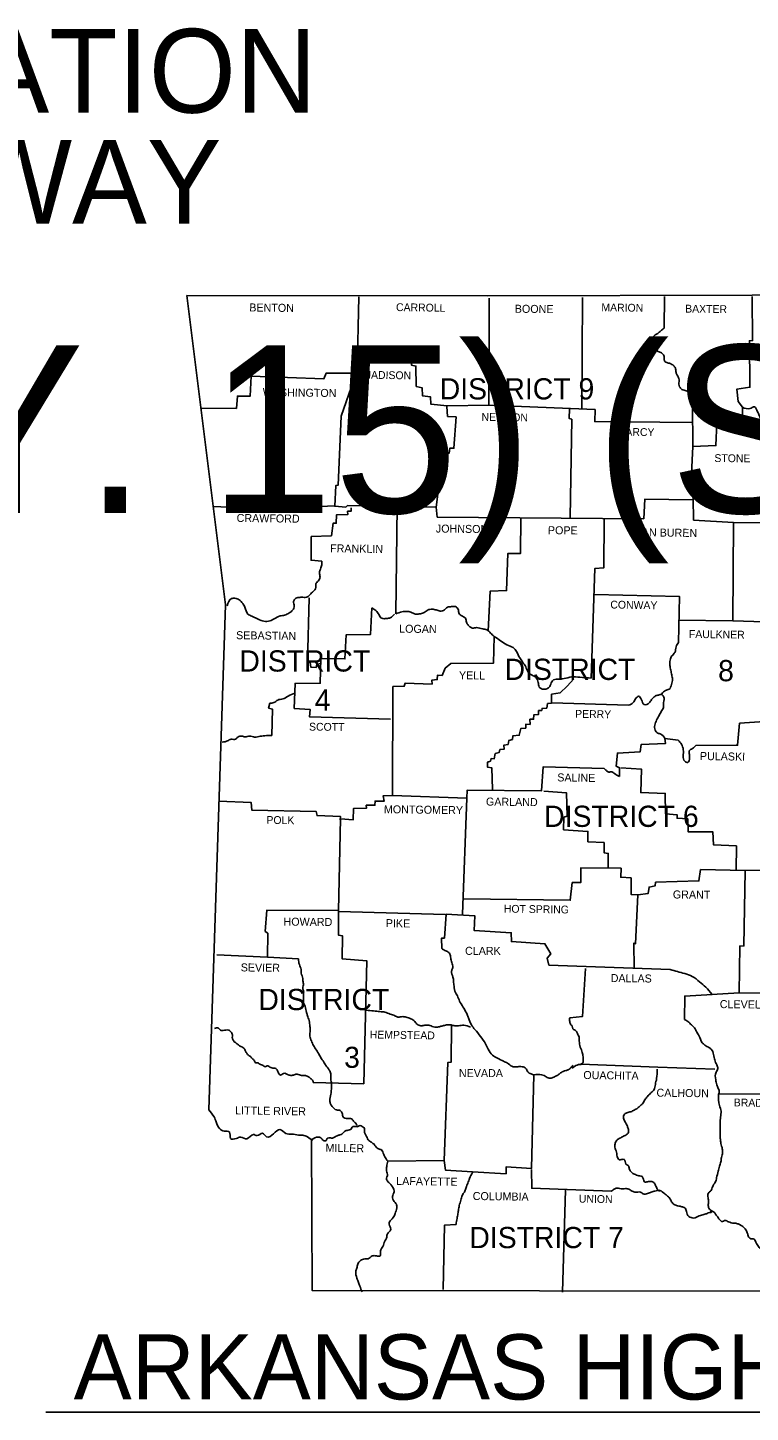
# Model space of a CAD drawing. Extents: x 1127717 to 1741049, y 2026793 to 2244711.
# Drawn here: x 1352440 to 1371845, y 2119549 to 2156746 of the extents above; entities that cross this region are included whole.
import ezdxf

# ---------------------------------------------------------------- set-up
doc = ezdxf.new("R2010")
doc.units = 0
doc.layers.add('R_Draft', color=7, linetype='Continuous')

msp = doc.modelspace()

# ---------------------------------------------------------------- linework, layer by layer
at = {"layer": 'R_Draft'}
msp.add_line((1352928, 2119549), (1385989, 2119549), dxfattribs=at)
for points in [[(1356715, 2149549), (1364800, 2149544), (1371895, 2149559), (1380265, 2149689), (1384145, 2149779)], [(1357300, 2127674), (1357750, 2141239), (1356715, 2149549)], [(1361330, 2149519), (1361285, 2147494)], [(1361320, 2147989), (1362550, 2147949), (1362580, 2147789), (1362750, 2147784), (1362745, 2147684), (1362865, 2147654), (1362875, 2147109), (1363030, 2147074), (1363040, 2146859), (1363260, 2146829), (1363270, 2146629), (1363705, 2146584), (1364825, 2146609), (1364835, 2149484)], [(1367340, 2149494), (1367325, 2146524)], [(1369540, 2149529), (1369530, 2148674)], [(1370380, 2137464), (1371505, 2137469), (1371555, 2138059), (1372225, 2138109), (1372225, 2140789), (1371375, 2140814), (1371390, 2143449), (1370320, 2143519), (1370305, 2144699), (1370270, 2144759), (1370300, 2145499), (1370920, 2145519), (1370945, 2146129), (1371625, 2146154), (1371635, 2146549), (1371515, 2146704), (1371485, 2147039), (1371835, 2147089), (1371820, 2148334), (1371905, 2148339), (1371895, 2149529)], [(1363435, 2143599), (1363410, 2143864), (1361025, 2143909), (1360980, 2143864), (1360685, 2143889), (1360715, 2144449), (1360775, 2144454), (1360855, 2146309), (1361260, 2147469), (1360455, 2147464), (1360395, 2147314), (1358445, 2147384), (1358415, 2146849), (1358070, 2146849), (1358045, 2146519), (1357110, 2146524)], [(1370300, 2145499), (1370295, 2146624)], [(1363695, 2146574), (1363715, 2146304), (1363945, 2146289), (1363885, 2145449), (1363780, 2145454), (1363760, 2145319), (1363640, 2145319), (1363635, 2145089), (1363560, 2145084), (1363535, 2144789), (1363425, 2144774), (1363410, 2144324), (1363460, 2144289), (1363410, 2143864)], [(1364825, 2146609), (1367675, 2146489), (1367670, 2146164), (1370285, 2146144)], [(1366990, 2146504), (1366985, 2146244), (1367050, 2146229), (1367010, 2143589)], [(1370300, 2144064), (1369010, 2144079), (1368985, 2143554), (1363435, 2143599)], [(1357440, 2143884), (1359715, 2143779), (1359725, 2143859), (1360675, 2143904)], [(1361125, 2143844), (1361125, 2143754), (1361030, 2143754), (1361035, 2143664), (1360730, 2143659), (1360725, 2143434), (1360640, 2143434), (1360595, 2143099), (1360055, 2143074), (1360050, 2142439), (1360340, 2142419)], [(1362325, 2140999), (1362360, 2143884)], [(1365680, 2143581), (1365675, 2142624), (1365330, 2142619), (1365300, 2141624), (1364860, 2141609), (1364808, 2140546)], [(1367920, 2143534), (1367910, 2142234), (1367670, 2142214), (1367575, 2139274)], [(1371390, 2143449), (1373960, 2143434), (1374180, 2143539), (1374165, 2141584), (1374015, 2141519), (1373880, 2141404), (1373835, 2141359), (1373830, 2140799), (1372195, 2140799)], [(1360000, 2141429), (1359950, 2139709), (1360025, 2139689), (1360040, 2139569), (1360190, 2139559), (1360205, 2139644), (1360325, 2139664)], [(1367660, 2141519), (1369945, 2141464), (1369915, 2140229)], [(1361680, 2141159), (1361645, 2140444), (1360995, 2140439), (1360960, 2139789), (1360315, 2139804), (1360295, 2139134), (1359620, 2139129), (1359600, 2138459), (1360025, 2138434), (1360010, 2138229), (1362180, 2138169)], [(1369920, 2140834), (1371375, 2140814)], [(1357515, 2131839), (1358880, 2131779), (1358885, 2132419), (1358815, 2132469), (1358860, 2133039), (1360785, 2133034), (1360840, 2135494), (1361180, 2135464), (1361185, 2135769), (1361535, 2135779), (1361530, 2135859), (1361765, 2135859), (1361770, 2135969), (1362010, 2135964), (1361990, 2136114), (1362240, 2136119), (1362250, 2139044), (1362550, 2139054), (1362575, 2139134), (1363300, 2139114), (1363295, 2139219), (1363440, 2139234), (1363445, 2139349), (1363570, 2139339), (1363655, 2139539), (1363805, 2139669), (1364945, 2139674), (1364965, 2140394)], [(1367110, 2139254), (1366930, 2139059), (1366735, 2138874), (1366510, 2138839), (1366510, 2138604), (1366400, 2138589), (1366380, 2138469), (1366255, 2138459), (1366245, 2138404), (1366160, 2138399), (1366155, 2138294), (1366035, 2138289), (1366025, 2138169), (1365925, 2138169), (1365930, 2138029), (1365820, 2138039), (1365815, 2137929), (1365680, 2137919), (1365640, 2137739), (1365470, 2137724), (1365455, 2137624), (1365365, 2137599), (1365340, 2137494), (1365225, 2137469), (1365235, 2137364), (1365120, 2137354), (1365100, 2137274), (1364995, 2137244), (1364970, 2137109), (1364890, 2137114), (1364865, 2137044), (1364790, 2137019), (1364785, 2136884), (1364900, 2136864), (1364920, 2136284)], [(1358995, 2137734), (1359010, 2138439), (1358910, 2138469), (1358940, 2138604)], [(1368575, 2138544), (1366515, 2138609)], [(1368330, 2136634), (1368330, 2136864), (1368240, 2136909), (1368275, 2137259), (1368890, 2137294), (1368910, 2137489), (1369565, 2137514), (1369550, 2137649), (1369910, 2137609)], [(1371480, 2137474), (1371505, 2137499)], [(1364230, 2136044), (1364240, 2136259), (1366240, 2136249), (1366285, 2136894), (1367920, 2136844)], [(1368365, 2136859), (1368925, 2136824), (1368905, 2136199), (1369560, 2136174), (1369570, 2135629), (1369880, 2135604), (1369880, 2135509), (1370170, 2135489), (1370180, 2135139), (1370840, 2135139), (1370860, 2134794), (1371470, 2134764), (1371465, 2134114)], [(1366300, 2136239), (1366905, 2136194), (1366925, 2135564), (1366840, 2135534), (1366830, 2135199), (1367485, 2135154), (1367485, 2134879), (1367920, 2134854), (1367925, 2134579), (1368030, 2134564), (1368025, 2134194)], [(1357575, 2135964), (1358440, 2135934), (1358460, 2135724), (1360190, 2135689), (1360210, 2135579), (1360840, 2135559), (1360835, 2135464)], [(1364230, 2136044), (1362240, 2136119)], [(1364115, 2132929), (1364230, 2136044)], [(1377430, 2134689), (1375540, 2134739), (1375530, 2134124), (1371705, 2134109)], [(1364150, 2133344), (1367010, 2133304), (1367065, 2133779), (1367290, 2133779), (1367295, 2134179), (1368375, 2134164), (1368365, 2133924), (1368645, 2133904), (1368645, 2133464), (1368825, 2133449)], [(1371705, 2134109), (1370510, 2134129), (1370465, 2133824), (1369300, 2133789), (1369290, 2133689), (1369125, 2133659), (1369105, 2133489), (1368825, 2133449)], [(1371705, 2134099), (1371675, 2132079), (1371560, 2132074), (1371545, 2130819)], [(1368825, 2133449), (1368765, 2132139), (1368720, 2132154), (1368725, 2131474)], [(1360785, 2133034), (1360785, 2132369), (1360895, 2132349), (1360885, 2131729), (1361545, 2131679), (1361465, 2128374), (1360105, 2128409)], [(1360795, 2132999), (1363655, 2132924)], [(1363560, 2132009), (1363550, 2132284), (1363630, 2132289), (1363680, 2132934), (1364450, 2132884), (1364430, 2132489), (1365425, 2132434), (1365430, 2132194), (1366330, 2132139), (1366485, 2131869), (1366390, 2131749), (1366435, 2131564), (1369695, 2131444)], [(1358880, 2131779), (1359710, 2131729)], [(1367415, 2131469), (1367340, 2130184), (1366995, 2130144)], [(1370825, 2130774), (1370085, 2130729), (1370080, 2130104)], [(1370815, 2130774), (1371545, 2130819)], [(1371545, 2130819), (1373315, 2130809)], [(1363825, 2129954), (1363815, 2128959), (1363725, 2128949), (1363625, 2126314)], [(1367290, 2128899), (1369360, 2128824), (1370895, 2128764)], [(1364385, 2126014), (1365285, 2125959), (1365290, 2126144), (1365965, 2126099), (1366030, 2128619)], [(1370995, 2128099), (1373255, 2128104)], [(1378400, 2122794), (1360075, 2122824), (1360065, 2126869)], [(1364385, 2126014), (1363660, 2126054), (1363625, 2126314), (1362110, 2126299)], [(1368110, 2125489), (1365975, 2125569), (1365965, 2126074)], [(1366885, 2125524), (1366805, 2122779)], [(1363600, 2122849), (1363635, 2124579), (1363945, 2124599)]]:
    msp.add_lwpolyline(points, dxfattribs=at)
for points in [[(1369530, 2148674), (1369440, 2148599), (1369360, 2148529), (1369240, 2148444), (1369225, 2148364), (1369265, 2148284), (1369305, 2148219), (1369320, 2148129), (1369355, 2148054), (1369440, 2148024), (1369510, 2147959), (1369535, 2147869), (1369545, 2147784), (1369625, 2147744), (1369715, 2147714), (1369800, 2147654), (1369840, 2147579), (1369850, 2147484), (1369885, 2147409), (1369925, 2147319), (1369935, 2147244), (1369925, 2147169), (1369945, 2147099), (1370010, 2147029), (1370125, 2146994), (1370205, 2146944), (1370260, 2146874), (1370225, 2146789), (1370230, 2146714), (1370275, 2146624)], [(1371635, 2146549), (1371835, 2146514), (1371955, 2146559), (1372040, 2146429), (1372085, 2146329), (1372160, 2146184), (1372280, 2146139), (1372370, 2146059), (1372370, 2145974), (1372290, 2145894), (1372230, 2145814), (1372250, 2145719), (1372270, 2145589), (1372270, 2145464), (1372240, 2145349), (1372215, 2145244), (1372240, 2145154), (1372335, 2145169), (1372435, 2145244), (1372540, 2145244), (1372640, 2145189), (1372745, 2145094), (1372850, 2145114), (1372935, 2145139), (1373055, 2145174), (1373140, 2145129), (1373215, 2145069), (1373305, 2144974), (1373390, 2144914), (1373500, 2144859), (1373635, 2144824), (1373760, 2144739), (1373780, 2144594), (1373775, 2144469), (1373765, 2144314), (1373755, 2144144), (1373770, 2143979), (1373825, 2143869), (1373895, 2143739), (1373915, 2143619), (1373910, 2143429)], [(1360340, 2142419), (1360340, 2142314), (1360300, 2142204), (1360275, 2142109), (1360290, 2141984), (1360245, 2141884), (1360180, 2141804), (1360180, 2141704), (1360105, 2141599), (1360025, 2141519), (1359955, 2141454), (1359830, 2141444), (1359725, 2141439), (1359620, 2141404), (1359580, 2141329), (1359600, 2141214), (1359560, 2141104), (1359455, 2141019), (1359340, 2140964), (1359220, 2140944), (1359055, 2140864), (1358905, 2140799), (1358745, 2140809), (1358595, 2140874), (1358460, 2140934), (1358355, 2140994), (1358270, 2141179), (1358215, 2141279), (1358120, 2141379), (1358005, 2141419), (1357910, 2141409), (1357795, 2141214)], [(1361680, 2141159), (1361790, 2141089), (1361875, 2140974), (1361950, 2140879), (1362075, 2140874), (1362175, 2140894), (1362290, 2140994)], [(1364965, 2140394), (1364870, 2140484), (1364770, 2140569), (1364660, 2140594), (1364490, 2140629), (1364380, 2140619), (1364315, 2140649), (1364270, 2140699), (1364225, 2140774), (1364200, 2140879), (1364115, 2140934), (1364020, 2141019), (1364005, 2141109), (1363930, 2141194), (1363825, 2141194), (1363705, 2141174), (1363635, 2141109), (1363515, 2141074), (1363405, 2141104), (1363300, 2141124), (1363190, 2141104), (1363090, 2141039), (1362990, 2141004), (1362855, 2140994), (1362730, 2141044), (1362610, 2141064), (1362490, 2141054), (1362325, 2140999)], [(1364965, 2140394), (1365140, 2140274), (1365305, 2140169), (1365475, 2140094), (1365570, 2139984), (1365655, 2139814), (1365725, 2139709), (1365815, 2139579), (1365880, 2139434), (1365985, 2139354), (1366095, 2139284), (1366150, 2139159), (1366175, 2139034), (1366295, 2138974), (1366410, 2138999), (1366475, 2139074), (1366535, 2139204), (1366670, 2139244), (1366845, 2139259), (1367045, 2139304), (1367265, 2139294), (1367575, 2139274)], [(1369915, 2140229), (1369850, 2140114), (1369820, 2139964), (1369740, 2139869), (1369690, 2139759), (1369685, 2139614), (1369710, 2139484), (1369735, 2139359), (1369755, 2139244), (1369730, 2139099), (1369665, 2138974), (1369565, 2138939), (1369470, 2138854)], [(1358940, 2138604), (1359050, 2138614), (1359155, 2138684), (1359295, 2138714), (1359435, 2138789), (1359610, 2138869)], [(1368575, 2138544), (1368700, 2138614), (1368765, 2138719), (1368845, 2138784), (1368925, 2138694), (1368995, 2138564), (1369070, 2138564), (1369165, 2138654), (1369225, 2138734), (1369300, 2138794), (1369380, 2138819), (1369465, 2138829), (1369530, 2138734), (1369510, 2138584), (1369510, 2138484), (1369455, 2138379), (1369395, 2138269), (1369330, 2138144), (1369280, 2138009), (1369290, 2137879), (1369360, 2137794), (1369440, 2137769), (1369550, 2137659)], [(1358995, 2137734), (1358850, 2137729), (1358685, 2137709), (1358535, 2137689), (1358400, 2137714), (1358275, 2137694), (1358190, 2137714), (1358085, 2137689), (1358025, 2137629), (1357900, 2137629), (1357810, 2137589), (1357665, 2137554)], [(1369910, 2137609), (1369995, 2137499), (1370045, 2137349), (1370045, 2137179), (1370085, 2137039), (1370165, 2137009), (1370215, 2137129), (1370205, 2137249), (1370205, 2137319), (1370290, 2137379), (1370380, 2137464)], [(1367920, 2136844), (1367980, 2136789), (1368045, 2136749), (1368125, 2136754), (1368200, 2136709), (1368330, 2136634)], [(1366030, 2128619), (1365960, 2128639), (1365870, 2128699), (1365820, 2128789), (1365715, 2128834), (1365600, 2128834), (1365445, 2128844), (1365325, 2128929), (1365220, 2128979), (1365055, 2129064), (1364925, 2129144), (1364810, 2129304), (1364735, 2129449), (1364600, 2129644), (1364450, 2129834), (1364355, 2129959), (1364280, 2130144), (1364240, 2130234), (1364155, 2130404), (1364055, 2130559), (1363995, 2130704), (1363930, 2130824), (1363890, 2130999), (1363875, 2131129), (1363860, 2131239), (1363820, 2131399), (1363850, 2131469), (1363840, 2131599), (1363805, 2131724), (1363785, 2131839), (1363735, 2131914), (1363640, 2131959), (1363560, 2132009)], [(1359710, 2131729), (1359735, 2131579), (1359780, 2131449), (1359785, 2131349), (1359830, 2131199), (1359830, 2131144), (1359845, 2131034), (1359825, 2130974), (1359850, 2130854), (1359845, 2130764), (1359845, 2130689), (1359850, 2130564), (1359890, 2130454), (1359930, 2130289), (1359955, 2130204), (1359995, 2130074), (1360020, 2129914), (1360025, 2129794), (1360015, 2129684), (1360045, 2129559), (1360100, 2129434), (1360170, 2129314), (1360255, 2129179), (1360315, 2129074), (1360390, 2128959), (1360450, 2128864), (1360540, 2128744), (1360580, 2128644), (1360580, 2128504), (1360600, 2128374), (1360595, 2128229), (1360585, 2128099), (1360550, 2127919), (1360575, 2127834), (1360670, 2127709), (1360730, 2127674), (1360835, 2127654), (1360885, 2127584), (1360915, 2127479), (1361020, 2127444), (1361135, 2127434), (1361190, 2127374), (1361265, 2127294), (1361290, 2127254)], [(1369695, 2131444), (1370085, 2131334), (1370285, 2131259), (1370485, 2131114), (1370650, 2130969), (1370815, 2130784)], [(1361535, 2130349), (1361725, 2130334), (1361900, 2130314), (1362035, 2130299), (1362175, 2130249), (1362300, 2130204), (1362380, 2130169), (1362515, 2130179), (1362630, 2130154), (1362760, 2130109), (1362855, 2130024), (1362915, 2129959), (1363030, 2129934), (1363125, 2129949), (1363240, 2129939), (1363370, 2129899), (1363475, 2129904), (1363560, 2129924), (1363660, 2129949), (1363785, 2129959), (1363880, 2129939), (1364005, 2129934), (1364150, 2129949), (1364330, 2129899)], [(1357455, 2129864), (1357565, 2129869), (1357640, 2129804), (1357685, 2129809), (1357765, 2129819), (1357840, 2129814), (1357895, 2129769), (1357940, 2129689), (1357935, 2129614), (1357940, 2129584), (1357975, 2129519), (1358035, 2129469), (1358100, 2129419), (1358160, 2129379), (1358260, 2129314), (1358270, 2129294), (1358310, 2129214), (1358360, 2129149), (1358420, 2129109), (1358485, 2129039), (1358515, 2129009), (1358565, 2128939), (1358620, 2128934), (1358695, 2128889), (1358750, 2128874), (1358810, 2128834), (1358870, 2128854), (1358945, 2128824), (1359045, 2128794), (1359100, 2128784), (1359165, 2128689), (1359230, 2128609), (1359310, 2128654), (1359460, 2128609), (1359555, 2128604), (1359640, 2128629), (1359705, 2128624), (1359825, 2128594), (1359900, 2128594), (1359980, 2128564), (1360055, 2128504), (1360105, 2128439), (1360105, 2128409)], [(1366995, 2130144), (1366995, 2130049), (1367030, 2129959), (1367065, 2129919), (1367080, 2129854), (1367125, 2129824), (1367190, 2129764), (1367225, 2129679), (1367250, 2129624), (1367250, 2129554), (1367255, 2129484), (1367265, 2129399), (1367325, 2129249), (1367340, 2129189), (1367350, 2129139), (1367355, 2129054), (1367355, 2128954), (1367290, 2128899)], [(1370080, 2130104), (1370195, 2130029), (1370290, 2129929), (1370360, 2129854), (1370405, 2129769), (1370465, 2129669), (1370550, 2129479), (1370625, 2129414), (1370730, 2129349), (1370795, 2129304), (1370860, 2129159), (1370890, 2129014), (1370945, 2128884), (1370970, 2128784), (1370925, 2128684), (1370915, 2128484), (1370945, 2128349), (1370985, 2128249), (1371010, 2128134), (1370995, 2128099)], [(1367085, 2128874), (1367030, 2128809), (1366965, 2128754), (1366890, 2128729), (1366820, 2128709), (1366730, 2128649), (1366660, 2128599), (1366565, 2128554), (1366475, 2128524), (1366365, 2128559), (1366305, 2128594), (1366240, 2128619), (1366030, 2128619)], [(1367065, 2128794), (1367195, 2128879), (1367340, 2128899)], [(1369340, 2128764), (1369330, 2128514), (1369295, 2128359), (1369260, 2128219), (1369185, 2128139), (1369105, 2128059), (1369030, 2127969), (1368965, 2127859), (1368900, 2127789), (1368815, 2127719), (1368730, 2127669), (1368635, 2127624), (1368530, 2127599), (1368455, 2127544), (1368450, 2127424), (1368535, 2127254), (1368565, 2127174), (1368575, 2127079), (1368540, 2127024), (1368460, 2126979), (1368365, 2126924), (1368280, 2126874), (1368220, 2126789), (1368210, 2126674), (1368250, 2126539), (1368265, 2126459), (1368330, 2126334), (1368380, 2126339), (1368470, 2126334), (1368480, 2126309), (1368485, 2126284), (1368505, 2126219), (1368580, 2126164), (1368590, 2126114), (1368635, 2126019), (1368710, 2125954), (1368765, 2125934), (1368880, 2125899), (1368940, 2125884), (1369005, 2125739), (1369085, 2125744), (1369145, 2125754), (1369245, 2125729), (1369290, 2125669), (1369335, 2125569), (1369395, 2125499), (1369435, 2125499)], [(1370995, 2128099), (1371015, 2127789), (1371060, 2127639), (1371045, 2127479), (1371040, 2127324), (1371040, 2127184), (1371040, 2127049), (1371040, 2126909), (1371050, 2126809), (1371085, 2126664), (1371100, 2126529), (1371070, 2126399), (1371055, 2126279), (1371015, 2126159), (1370980, 2126024), (1370940, 2125849), (1370905, 2125734), (1370835, 2125614), (1370790, 2125504), (1370720, 2125434), (1370710, 2125314), (1370725, 2125204), (1370715, 2125104), (1370750, 2125009), (1370840, 2124944)], [(1360065, 2126869), (1360085, 2126859), (1359990, 2126924), (1359860, 2126989), (1359715, 2126999), (1359530, 2127024), (1359375, 2127039), (1359215, 2127144), (1359045, 2127034), (1358855, 2126954), (1358745, 2127044), (1358600, 2126984), (1358500, 2127014), (1358325, 2126894), (1358160, 2126939), (1358040, 2126904), (1357890, 2126909), (1357860, 2127079), (1357715, 2127104), (1357590, 2127174), (1357505, 2127349), (1357445, 2127484), (1357300, 2127674)], [(1360065, 2126869), (1360240, 2126944), (1360315, 2126919), (1360380, 2126854), (1360455, 2126854), (1360495, 2126914), (1360570, 2126919), (1360630, 2126914), (1360695, 2126954), (1360750, 2126979), (1360825, 2127004), (1360880, 2127024), (1360930, 2127079), (1361020, 2127124), (1361125, 2127159), (1361155, 2127209), (1361205, 2127229), (1361305, 2127224), (1361370, 2127254), (1361425, 2127229), (1361475, 2127194), (1361485, 2127064), (1361525, 2126994), (1361585, 2126869), (1361670, 2126804), (1361750, 2126739), (1361780, 2126699), (1361865, 2126624), (1361940, 2126599), (1361975, 2126544), (1362030, 2126414), (1362110, 2126299)], [(1362110, 2126299), (1362080, 2126154), (1362075, 2126039), (1362100, 2125904), (1362075, 2125839), (1362115, 2125744), (1362190, 2125669), (1362245, 2125589), (1362280, 2125474), (1362235, 2125344), (1362285, 2125209), (1362330, 2125159), (1362355, 2125079), (1362320, 2124924), (1362275, 2124809), (1362175, 2124694), (1362145, 2124639), (1362160, 2124564), (1362185, 2124444), (1362160, 2124409), (1362095, 2124324), (1362075, 2124229), (1362030, 2124149), (1361980, 2124004), (1361915, 2123884), (1361905, 2123749), (1361805, 2123749), (1361690, 2123749), (1361585, 2123674), (1361490, 2123669), (1361375, 2123624), (1361305, 2123529), (1361280, 2123424), (1361250, 2123324), (1361280, 2123154), (1361325, 2123034), (1361360, 2122939), (1361420, 2122784)], [(1363945, 2124599), (1363970, 2124759), (1363995, 2124884), (1364010, 2125004), (1364040, 2125139), (1364085, 2125284), (1364125, 2125404), (1364180, 2125489), (1364215, 2125589), (1364260, 2125709), (1364305, 2125834), (1364385, 2125994)], [(1368110, 2125489), (1368190, 2125544), (1368265, 2125574), (1368340, 2125559), (1368420, 2125549), (1368490, 2125559), (1368580, 2125544), (1368655, 2125499), (1368740, 2125464), (1368825, 2125464), (1368900, 2125464), (1368965, 2125419), (1369085, 2125424), (1369185, 2125464), (1369285, 2125494), (1369420, 2125509), (1369540, 2125424), (1369625, 2125354), (1369695, 2125274), (1369745, 2125184), (1369800, 2125134), (1369890, 2125099), (1369960, 2125084), (1370045, 2125059), (1370090, 2125039), (1370130, 2124944), (1370195, 2124814), (1370320, 2124769), (1370475, 2124829), (1370600, 2124864), (1370690, 2124894), (1370745, 2124914), (1370795, 2124919), (1370780, 2124929), (1370840, 2124944), (1370895, 2124904), (1370930, 2124849), (1370990, 2124769), (1371045, 2124699), (1371100, 2124674), (1371155, 2124704), (1371230, 2124679), (1371295, 2124654), (1371370, 2124634), (1371435, 2124629), (1371520, 2124609), (1371585, 2124574), (1371645, 2124539), (1371705, 2124474), (1371765, 2124374), (1371785, 2124294), (1371855, 2124214), (1371920, 2124214), (1372015, 2124084), (1372050, 2124034), (1372125, 2123944), (1372180, 2123944), (1372285, 2123924)]]:
    msp.add_spline(points, degree=3, dxfattribs=at)

# ---------------------------------------------------------------- texts
for s, height, p in [('ARKANSAS DEPARTMENT OF TRANSPORTATION', 2250, (1288656, 2154463)), ('CONSTRUCTION PLANS FOR STATE HIGHWAY', 2250, (1289777, 2151483)), ('I-40 STR. & APPRS. (HWY. 15) (S)', 4500, (1281068, 2143713)), ('DISTRICT 9', 570, (1363505, 2146759)), ('DISTRICT', 570, (1358125, 2139449)), ('DISTRICT', 570, (1365245, 2139224)), ('8', 570, (1370980, 2139189)), ('4', 570, (1360150, 2138399)), ('DISTRICT 6', 570, (1366309, 2135276)), ('CLARK', 215, (1364185, 2131839)), ('DISTRICT', 570, (1358635, 2130354)), ('3', 565, (1360940, 2128804)), ('NEVADA', 215, (1364020, 2128554)), ('DISTRICT 7', 570, (1364300, 2123959)), ('ARKANSAS HIGHWAY DISTRICT 6', 1750, (1353673, 2119894))]:
    msp.add_text(s, height=height, dxfattribs=at).set_placement(p)
for s, height, rotation, p in [('BENTON', 215, 359.2527, (1358390, 2149124)), ('CARROLL', 210, 359.1481, (1362330, 2149134)), ('BOONE', 215, 359.4001, (1365520, 2149089)), ('MARION', 210, 359.1854, (1367845, 2149129)), ('BAXTER', 210, 359.2559, (1370095, 2149094)), ('MADISON', 210, 359.0906, (1361425, 2147319)), ('WASHINGTON', 215, 359.232, (1358750, 2146849)), ('NEWTON', 210, 359.2717, (1364625, 2146184)), ('SEARCY', 210, 359.2527, (1368115, 2145789)), ('STONE', 210, 359.4001, (1370880, 2145079)), ('CRAWFORD', 215, 359.2771, (1358050, 2143469)), ('JOHNSON', 215, 359.3514, (1363400, 2143184)), ('POPE', 215, 359.6155, (1366410, 2143139)), ('VAN BUREN', 215, 359.3508, (1368740, 2143084)), ('FRANKLIN', 215, 359.1815, (1360560, 2142654)), ('CONWAY', 210, 359.0371, (1368085, 2141144)), ('LOGAN', 215, 359.3969, (1362415, 2140494)), ('SEBASTIAN', 215, 359.2816, (1358035, 2140319)), ('FAULKNER', 210, 359.2486, (1370195, 2140354)), ('YELL', 215, 359.1987, (1364020, 2139244)), ('SCOTT', 210, 359.4063, (1359995, 2137864)), ('PERRY', 210, 359.0858, (1367140, 2138209)), ('PULASKI', 215, 359.053, (1370490, 2137074)), ('SALINE', 215, 359.1491, (1366660, 2136499)), ('MONTGOMERY', 215, 359.2944, (1362005, 2135644)), ('GARLAND', 215, 359.3658, (1364745, 2135849)), ('POLK', 210, 359.2152, (1358850, 2135359)), ('GRANT', 215, 359.4032, (1369765, 2133354)), ('HOT SPRING', 210, 359.2216, (1365225, 2132974)), ('HOWARD', 215, 359.5145, (1359310, 2132624)), ('PIKE', 215, 359.0452, (1362055, 2132584)), ('SEVIER', 215, 359.4271, (1358160, 2131394)), ('DALLAS', 215, 359.2462, (1368095, 2131109)), ('CLEVELAND', 215, 359.3376, (1371025, 2130409)), ('HEMPSTEAD', 210, 359.1885, (1361625, 2129594)), ('OUACHITA', 215, 359.2043, (1367360, 2128504)), ('CALHOUN', 215, 359.3634, (1369325, 2128029)), ('LITTLE RIVER', 215.04, 359.1697, (1358010, 2127554)), ('BRADLEY', 210, 359.1449, (1371400, 2127769)), ('MILLER', 215, 359.1319, (1360435, 2126549)), ('LAFAYETTE', 215, 359.1839, (1362335, 2125659)), ('COLUMBIA', 215, 359.2125, (1364390, 2125254)), ('UNION', 210, 358.9584, (1367240, 2125184))]:
    msp.add_text(s, height=height, rotation=rotation, dxfattribs=at).set_placement(p)

doc.saveas('drawing.dxf')
